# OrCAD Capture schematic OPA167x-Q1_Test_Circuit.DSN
size A; title: OPA167x-Q1 Automotive, Low-Distortion Audio Operational; rev: 1.1; note: Datasheet: SBOS922   EVM: N/A
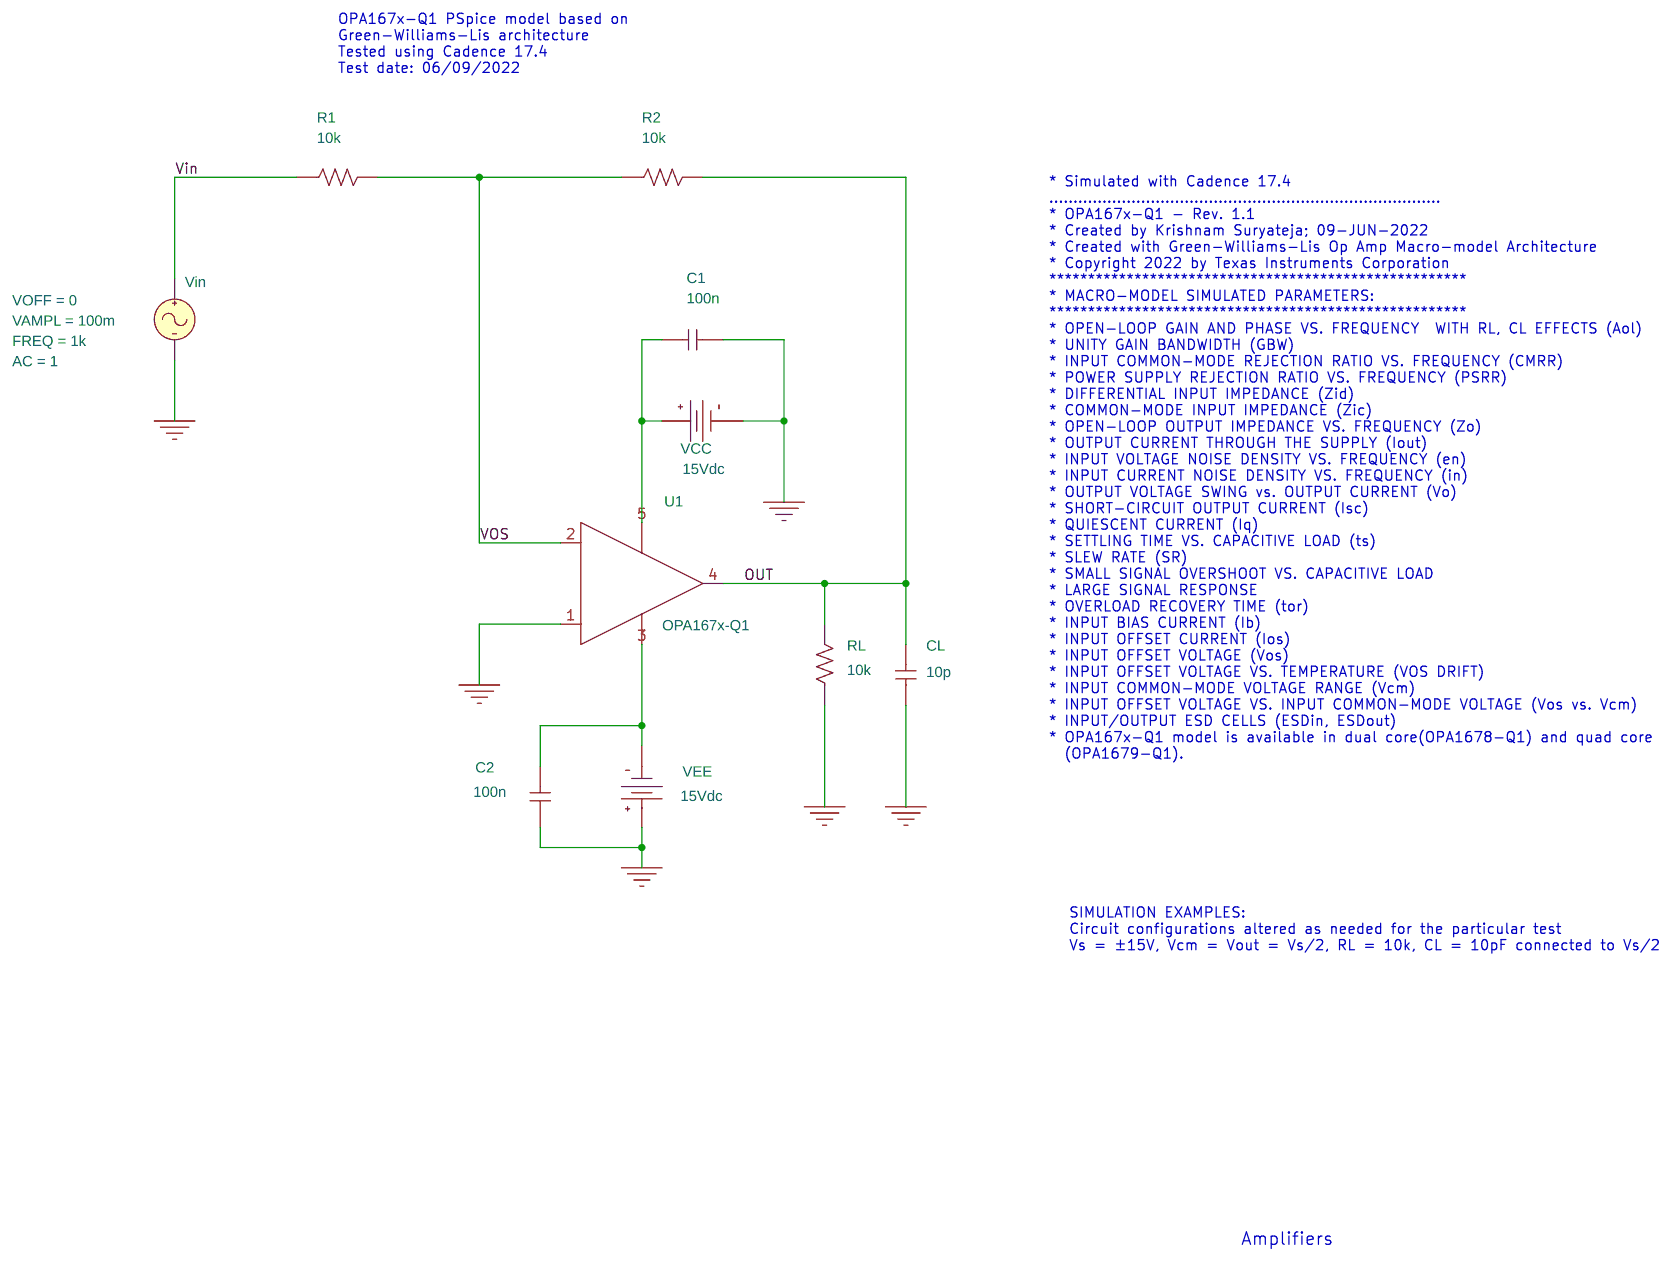
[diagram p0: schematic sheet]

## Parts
C1  100n  [cap196]
C2  100n  [cap196]
CL  10p  [cap196]
R1  10k  [AXRC05]
R2  10k  [AXRC05]
RL  10k  [AXRC05]
U1  OPA167x-Q1
VCC  VDC
VEE  VDC
Vin  VSIN

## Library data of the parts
C1 C2 CL = C
R1 R2 RL = R
U1 = OPA167x-Q1
VCC VEE = VDC: DC: 15Vdc
Vin = VSIN: AC: 1; FREQ: 1k; VAMPL: 100m; VOFF: 0

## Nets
Vin: R1.1 Vin.1(+)
0: C1.2 C2.1 CL.2 RL.1 U1.1(+) VCC.1(-) VEE.0(+) Vin.2(-)
OUT: CL.1 R2.2 RL.2 U1.4(OUT)
VOS: R1.2 R2.1 U1.2(-)
N27303: C1.1 U1.5(V+) VCC.0(+)
N27354: C2.2 U1.3(V-) VEE.1(-)

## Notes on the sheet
- OPA167x-Q1 PSpice model based on
  Green-Williams-Lis architecture
  Tested using Cadence 17.4
  Test date: 06/09/2022
- * Simulated with Cadence 17.4
  .................................................................................
  * OPA167x-Q1 - Rev. 1.1
  * Created by Krishnam Suryateja; 09-JUN-2022
  * Created with Green-Williams-Lis Op Amp Macro-model Architecture
  * Copyright 2022 by Texas Instruments Corporation
  ******************************************************
  * MACRO-MODEL SIMULATED PARAMETERS:
  ******************************************************
  * OPEN-LOOP GAIN AND PHASE VS. FREQUENCY  WITH RL, CL EFFECTS (Aol)
  * UNITY GAIN BANDWIDTH (GBW)
  * INPUT COMMON-MODE REJECTION RATIO VS. FREQUENCY (CMRR)
  * POWER SUPPLY REJECTION RATIO VS. FREQUENCY (PSRR)
  * DIFFERENTIAL INPUT IMPEDANCE (Zid)
  * COMMON-MODE INPUT IMPEDANCE (Zic)
  * OPEN-LOOP OUTPUT IMPEDANCE VS. FREQUENCY (Zo)
  * OUTPUT CURRENT THROUGH THE SUPPLY (Iout)
  * INPUT VOLTAGE NOISE DENSITY VS. FREQUENCY (en)
  * INPUT CURRENT NOISE DENSITY VS. FREQUENCY (in)
  * OUTPUT VOLTAGE SWING vs. OUTPUT CURRENT (Vo)
  * SHORT-CIRCUIT OUTPUT CURRENT (Isc)
  * QUIESCENT CURRENT (Iq)
  * SETTLING TIME VS. CAPACITIVE LOAD (ts)
  * SLEW RATE (SR)
  * SMALL SIGNAL OVERSHOOT VS. CAPACITIVE LOAD
  * LARGE SIGNAL RESPONSE
  * OVERLOAD RECOVERY TIME (tor)
  * INPUT BIAS CURRENT (Ib)
  * INPUT OFFSET CURRENT (Ios)
  * INPUT OFFSET VOLTAGE (Vos)
  * INPUT OFFSET VOLTAGE VS. TEMPERATURE (VOS DRIFT)
  * INPUT COMMON-MODE VOLTAGE RANGE (Vcm)
  * INPUT OFFSET VOLTAGE VS. INPUT COMMON-MODE VOLTAGE (Vos vs. Vcm)
  * INPUT/OUTPUT ESD CELLS (ESDin, ESDout)
  * OPA167x-Q1 model is available in dual core(OPA1678-Q1) and quad core
    (OPA1679-Q1).
- SIMULATION EXAMPLES:
  Circuit configurations altered as needed for the particular test
  Vs = ±15V, Vcm = Vout = Vs/2, RL = 10k, CL = 10pF connected to Vs/2
- Amplifiers
